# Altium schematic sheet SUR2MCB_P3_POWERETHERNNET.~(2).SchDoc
size 420 x 297 mm; Scale: 1:1; Разраб.: Иванов; Обозначение документа: АБВГ.123456.001 Э3; Пров.: Петров; Утв.: Сидоров; Наименование организации: ОАО "Концерн "МПО-Гидроприбор"; Перв. применение: АБВГ.123456.000; Наименование изделия 1: Плата; Наименование изделия 2: Схема электрическая; Наименование изделия 3: принципиальная; Нач. отд.: Нач. отд.; Фамилия нач. отд.: Сидоров
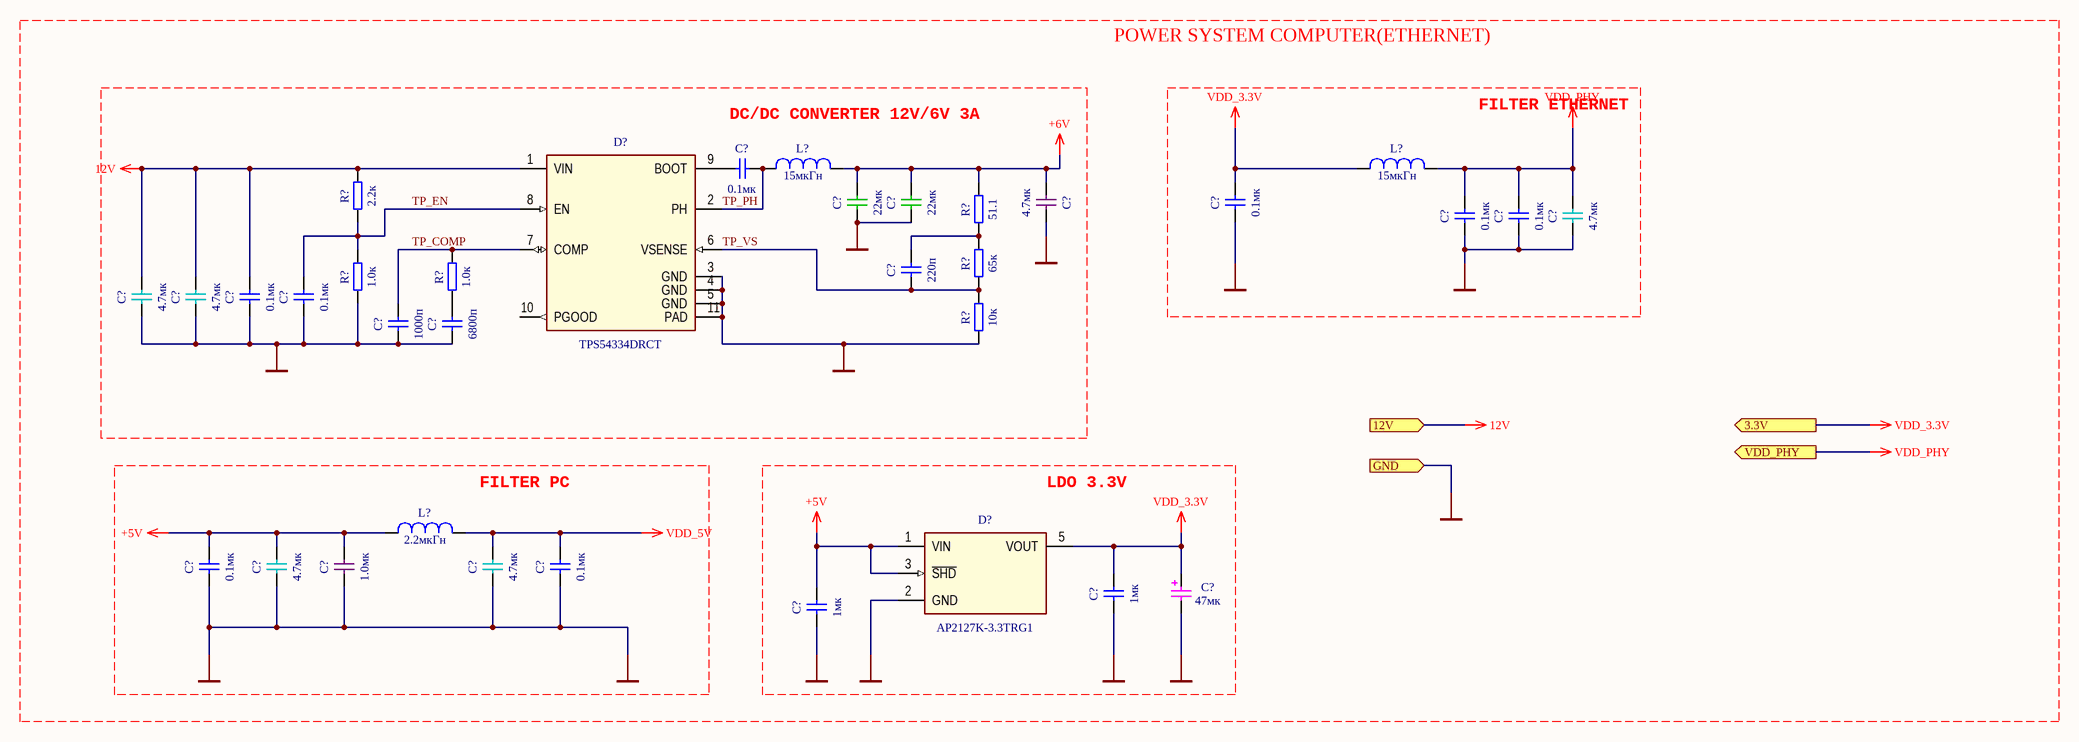
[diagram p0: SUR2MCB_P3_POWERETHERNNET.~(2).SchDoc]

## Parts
(Parts that share a designator on the sheet are numbered #1, #2 ... from top to bottom, then left to right.)
C?#1  value 0.1мк  [C0603]
C?#2  value 4.7мк  [C0805]
C?#3  value 22мк  [C1210]
C?#4  value 22мк  [C1210]
C?#5  value 0.1мк  [C0603]
C?#6  value 0.1мк  [C0603]
C?#7  value 0.1мк  [C0603]
C?#8  value 4.7мк  [C1206]
C?#9  value 220п  [C0603]
C?#10  value 4.7мк  [C1206]
C?#11  value 4.7мк  [C1206]
C?#12  value 0.1мк  [C0603]
C?#13  value 0.1мк  [C0603]
C?#14  value 1000п  [C0603]
C?#15  value 6800п  [C0603]
C?#16  value 0.1мк  [C0603]
C?#17  value 4.7мк  [C1206]
C?#18  value 1.0мк  [C0805]
C?#19  value 4.7мк  [C1206]
C?#20  value 0.1мк  [C0603]
C?#21  value 1мк  [C0603]
C?#22  value 47мк  [CAP_ELEC_SIZE_G]
C?#23  value 1мк  [C0603]
D?#1  value TPS54334DRCT  [SON-10-3X3-0.5-T-SPECIAL]
D?#2  value AP2127K-3.3TRG1  [TSOT23-5-1.4X3-0.95]
L?#1  value 15мкГн  [L-ASPI-0630LR]
L?#2  value 15мкГн  [L-ASPI-0630LR]
L?#3  value 2.2мкГн  [L1008]
R?#1  value 2.2к  [R0603]
R?#2  value 51.1  [R0603]
R?#3  value 65к  [R0603]
R?#4  value 1.0к  [R0603]
R?#5  value 1.0к  [R0603]
R?#6  value 10к  [R0603]

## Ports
3.3V (out), 12V (in), GND (in), VDD_PHY (out)

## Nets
12V: C?#10.2 C?#11.2 C?#12.2 D?#1.1(VIN) R?#1.1 ; port 12V
+5V: C?#16.2 C?#17.2 C?#18.2 C?#23.2 D?#2.1(VIN) D?#2.3(~{SHD}) L?#3.1
+6V: C?#2.1 C?#3.2 C?#4.2 L?#1.2 R?#2.1
GND: C?#2.2 C?#3.1 C?#4.1 C?#5.1 C?#6.1 C?#7.1 C?#8.1 C?#10.1 C?#11.1 C?#12.1 C?#13.1 C?#14.1 C?#15.1 C?#16.1 C?#17.1 C?#18.1 C?#19.1 C?#20.1 C?#21.1 C?#22.1 C?#23.1 D?#1.3(GND) D?#1.4(GND) D?#1.5(GND) D?#1.11(PAD) D?#2.2(GND) R?#4.2 R?#6.2 ; port GND
VDD_3.3V: C?#5.2 C?#21.2 C?#22.2 D?#2.5(VOUT) L?#2.1 ; port 3.3V
VDD_5V: C?#19.2 C?#20.2 L?#3.2
VDD_PHY: C?#6.2 C?#7.2 C?#8.2 L?#2.2 ; port VDD_PHY
TP_COMP: C?#14.2 D?#1.7(COMP) R?#5.1
TP_EN: C?#13.2 D?#1.8(EN) R?#1.2 R?#4.1
TP_PH: C?#1.2 D?#1.2(PH) L?#1.1
TP_VS: C?#9.1 D?#1.6(VSENSE) R?#3.2 R?#6.1
NetC?#1_1: C?#1.1 D?#1.9(BOOT)
NetC?#9_2: C?#9.2 R?#2.2 R?#3.1
NetC?#15_2: C?#15.2 R?#5.2

Not connected (* = marked no-connect by the designer): D?#1 10(PGOOD)

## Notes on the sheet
- POWER SYSTEM COMPUTER(ETHERNET)
- FILTER ETHERNET
- DC/DC CONVERTER 12V/6V 3A
- (near L?#3) FILTER PC
- LDO 3.3V

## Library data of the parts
C?#1 C?#5-C?#7 C?#12 C?#13 C?#16 C?#20 = C-0603: SMD X7R 0603 25В ±10%; ValueManufacturer: Murata Electronics; ValueManufacturerPartNumber: GCM188R71H; ValueDescription: X7R 0603 (1608)  25В  0.1мкФ ±10%; ValueType: Ceramic Capacitor
C?#2 = C-0805: SMD X7R 0805 50В ±10%; ValueManufacturer: Murata Electronics; ValueManufacturerPartNumber: GCM21BR71H; ValueDescription: X7R 0805 (2012)  50В  4.7мкФ ±10%; ValueType: Ceramic Capacitor
C?#3 C?#4 = C-1210: SMD X7R 1210 250В ±10%; ValueManufacturer: Murata Electronics; ValueManufacturerPartNumber: GCJ32DR72E; ValueDescription: X7R 1210 (3225)  250В  22мкФ ±10%; ValueType: Ceramic Capacitor
C?#8 C?#10 C?#11 C?#17 C?#19 = C-1206: SMD X7R 1206 100В ±10%; ValueManufacturer: Murata Electronics; ValueManufacturerPartNumber: GCM319R72A; ValueDescription: X7R 1206 (3216)  100В  4.7мкФ ±10%; ValueType: Ceramic Capacitor
C?#9 = C-0603: SMD X7R 0603 25В ±10%; ValueManufacturer: Murata Electronics; ValueManufacturerPartNumber: GCM188R71H; ValueDescription: X7R 0603 (1608)  25В  220пФ ±10%; ValueType: Ceramic Capacitor
C?#14 = C-0603: SMD X7R 0603 25В ±10%; ValueManufacturer: Murata Electronics; ValueManufacturerPartNumber: GCM188R71H; ValueDescription: X7R 0603 (1608)  25В  1000пФ ±10%; ValueType: Ceramic Capacitor
C?#15 = C-0603: SMD X7R 0603 25В ±10%; ValueManufacturer: Murata Electronics; ValueManufacturerPartNumber: GCM188R71H; ValueDescription: X7R 0603 (1608)  25В  6800пФ ±10%; ValueType: Ceramic Capacitor
C?#18 = C-0805: SMD X7R 0805 50В ±10%; ValueManufacturer: Murata Electronics; ValueManufacturerPartNumber: GCM21BR71H; ValueDescription: X7R 0805 (2012)  50В  1.0мкФ ±10%; ValueType: Ceramic Capacitor
C?#21 C?#23 = C-0603: SMD X7R 0603 25В ±10%; ValueManufacturer: Murata Electronics; ValueManufacturerPartNumber: GCM188R71H; ValueDescription: X7R 0603 (1608)  25В  1мкФ ±10%; ValueType: Ceramic Capacitor
C?#22 = C-EL-SMD-D10: SMD CAP ALUM 47UF 20% 50V 10.30x10.30mm; ValueManufacturer: Panasonic Electronic; ValueManufacturerPartNumber: EEE-FC1H470P; PowerVoltage: 50B; ValueDescription: EEE-FC1H470P  50B  47мкФ ±20%  10.30x10.30mm; ValueType: Electrolytic Capacitor
D?#1 = TPS54334DRCT: Step Down 4.2V~28V Input voltage 3A 570kHz; ValueManufacturer: Texas Instruments; PowerVoltage: 4.2V~28V 3A; ValueDescription: TPS54334DRCT  Преобразователь напряжения 4.2V~28V 3A  10-VSON EP (3x3mm); ValueType: Power Management
D?#2 = AP2127K-3.3TRG1: LDO 3.3V 300mA VINmax=6V SOT-23-5 SOT-753; ValueManufacturer: Diodes Incorporated; ValueDescription: AP2127K-3.3TRG1 Линейный преобразователь 3.3V 300mA  SOT-23-5 (SOT-753)  VINmax=6V; ValueType: Power Management
L?#1 L?#2 = L-ASPI-0630LR-150M: FIXED IND 15UH 3A 120 MOHM; ValueManufacturer: Abracon LLC; Tolerance: ±20%; ValueDescription: ASPI-0630LR-150M Индуктивность 15мкГн  7.20x6.65mm  3A  ±20%; ValueType: Inductor
L?#3 = L-CIG22B2R2MNE: FIXED IND 2.2UH 1.1A 183 MOHM; ValueManufacturer: Samsung Electro-Mechanics; Tolerance: ±20%; ValueDescription: CIG22B2R2MNE Индуктивность 2.2мкГн  1008 (2520)  1.1A  ±20%; ValueType: Inductor
R?#1 = R-0603-5%: SMD 0603 0.1Вт ±5% 75В; ValueManufacturer: Panasonic; ValueManufacturerPartNumber: ERJ-3GE; PowerVoltage: 0.1Вт 75В; ValueDescription: 0603 (1608)  0.1Вт 75В  2.2кОм ±5%; ValueType: Chip Resistor
R?#2 = R-0603-5%: SMD 0603 0.1Вт ±5% 75В; ValueManufacturer: Panasonic; ValueManufacturerPartNumber: ERJ-3GE; PowerVoltage: 0.1Вт 75В; ValueDescription: 0603 (1608)  0.1Вт 75В  51.1Ом ±5%; ValueType: Chip Resistor
R?#3 = R-0603-5%: SMD 0603 0.1Вт ±5% 75В; ValueManufacturer: Panasonic; ValueManufacturerPartNumber: ERJ-3GE; PowerVoltage: 0.1Вт 75В; ValueDescription: 0603 (1608)  0.1Вт 75В  65кОм ±5%; ValueType: Chip Resistor
R?#4 R?#5 = R-0603-5%: SMD 0603 0.1Вт ±5% 75В; ValueManufacturer: Panasonic; ValueManufacturerPartNumber: ERJ-3GE; PowerVoltage: 0.1Вт 75В; ValueDescription: 0603 (1608)  0.1Вт 75В  1.0кОм ±5%; ValueType: Chip Resistor
R?#6 = R-0603-5%: SMD 0603 0.1Вт ±5% 75В; ValueManufacturer: Panasonic; ValueManufacturerPartNumber: ERJ-3GE; PowerVoltage: 0.1Вт 75В; ValueDescription: 0603 (1608)  0.1Вт 75В  10кОм ±5%; ValueType: Chip Resistor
